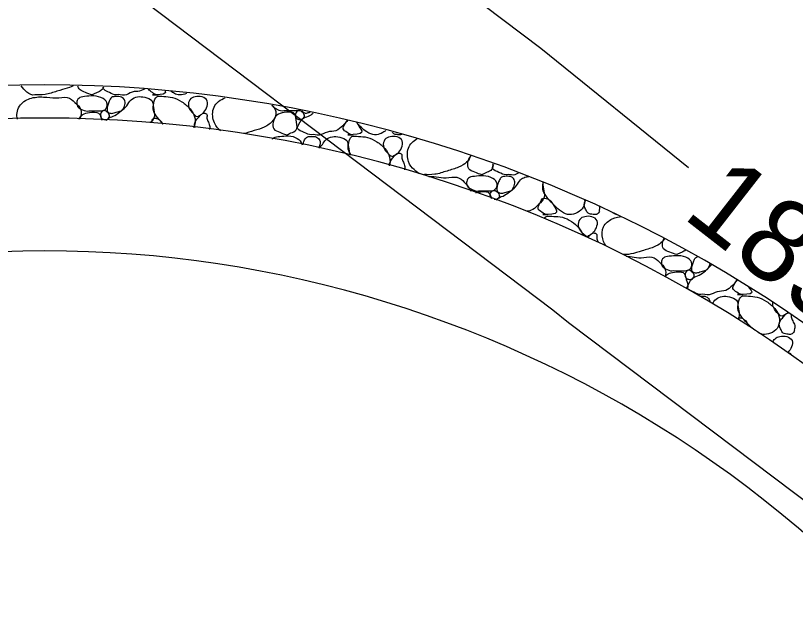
# Model space of a CAD drawing. Extents: x 1385284 to 1385995, y 1975154 to 1975620.
# Drawn here: x 1385467.93 to 1385491.41, y 1975551 to 1975568.95 of the extents above; entities that cross this region are included whole.
import ezdxf

# ---------------------------------------------------------------- set-up
doc = ezdxf.new("R2010")
doc.units = 0
for name, color, linetype in [('Default', 7, 'Continuous'), ('DTM_CONTOURS_MINOR', 7, 'Continuous'), ('R_Proposed Const Limits', 7, 'Continuous')]:
    doc.layers.add(name, color=color, linetype=linetype)

msp = doc.modelspace()

# ---------------------------------------------------------------- linework, layer by layer
at = {"layer": 'Default'}
for radius in [40, 39]:
    msp.add_arc((1385468.803, 1975526.863), radius, 324.5634, 101.9984, dxfattribs=at)
for points in [[(1385468.502, 1975566.57), (1385468.434, 1975566.535), (1385468.25, 1975566.649), (1385468.14, 1975566.768), (1385468.094, 1975566.834)], [(1385469.662, 1975566.836), (1385469.65, 1975566.829), (1385469.493, 1975566.763), (1385469.179, 1975566.681), (1385468.808, 1975566.552), (1385468.574, 1975566.567), (1385468.502, 1975566.57)], [(1385470.235, 1975566.566), (1385470.163, 1975566.576), (1385470.018, 1975566.645), (1385469.847, 1975566.701), (1385469.806, 1975566.8), (1385469.8, 1975566.83)], [(1385470.568, 1975566.798), (1385470.565, 1975566.771), (1385470.513, 1975566.693), (1385470.386, 1975566.638), (1385470.283, 1975566.59), (1385470.235, 1975566.566)], [(1385470.958, 1975566.566), (1385470.887, 1975566.561), (1385470.751, 1975566.641), (1385470.568, 1975566.716), (1385470.558, 1975566.792), (1385470.558, 1975566.798)], [(1385471.813, 1975566.745), (1385471.793, 1975566.731), (1385471.661, 1975566.655), (1385471.44, 1975566.682), (1385471.203, 1975566.506), (1385471.037, 1975566.586), (1385470.958, 1975566.566)], [(1385472.184, 1975566.566), (1385472.137, 1975566.565), (1385472.043, 1975566.636), (1385471.951, 1975566.699), (1385471.932, 1975566.74)], [(1385472.426, 1975566.684), (1385472.43, 1975566.667), (1385472.498, 1975566.561), (1385471.84, 1975566.574), (1385472.226, 1975566.563), (1385472.218, 1975566.566)], [(1385472.867, 1975566.566), (1385472.796, 1975566.562), (1385472.708, 1975566.601), (1385472.627, 1975566.654), (1385472.615, 1975566.662)], [(1385473.069, 1975566.609), (1385473.001, 1975566.579), (1385472.934, 1975566.565), (1385472.867, 1975566.566)], [(1385467.987, 1975565.831), (1385467.943, 1975565.953), (1385467.998, 1975566.257), (1385468.344, 1975566.489), (1385468.78, 1975566.517), (1385469.14, 1975566.445), (1385469.506, 1975566.538), (1385469.709, 1975566.333), (1385469.932, 1975566.144), (1385469.898, 1975565.923), (1385469.848, 1975565.828)], [(1385470.13, 1975566.083), (1385470.074, 1975566.059), (1385469.929, 1975566.117), (1385469.768, 1975566.203), (1385469.757, 1975566.369), (1385469.834, 1975566.501), (1385470.053, 1975566.52), (1385470.353, 1975566.55), (1385470.652, 1975566.427), (1385470.711, 1975566.241), (1385470.615, 1975566.074), (1385470.41, 1975566.082), (1385470.249, 1975566.077), (1385470.13, 1975566.083)], [(1385470.653, 1975565.794), (1385470.659, 1975565.802), (1385470.732, 1975565.882), (1385470.909, 1975565.927), (1385471.11, 1975566.086), (1385471.289, 1975566.228), (1385471.384, 1975566.434), (1385471.595, 1975566.527), (1385471.81, 1975566.501), (1385472.074, 1975566.415), (1385472.066, 1975566.187), (1385472.143, 1975565.915), (1385472.045, 1975565.782), (1385471.997, 1975565.728)], [(1385471.101, 1975566.083), (1385471.054, 1975566.068), (1385470.957, 1975566.045), (1385470.823, 1975565.991), (1385470.696, 1975566.033), (1385470.669, 1975566.139), (1385470.699, 1975566.253), (1385470.743, 1975566.38), (1385470.803, 1975566.505), (1385470.954, 1975566.521), (1385471.126, 1975566.517), (1385471.238, 1975566.39), (1385471.214, 1975566.23), (1385471.154, 1975566.113), (1385471.101, 1975566.083)], [(1385472.368, 1975565.685), (1385472.316, 1975565.742), (1385472.192, 1975565.878), (1385472.048, 1975566.09), (1385472.08, 1975566.316), (1385472.151, 1975566.558), (1385472.38, 1975566.506), (1385472.65, 1975566.511), (1385472.939, 1975566.366), (1385473.196, 1975566.155), (1385473.344, 1975565.896), (1385473.333, 1975565.665), (1385473.288, 1975565.59), (1385473.281, 1975565.579)], [(1385473.444, 1975565.937), (1385473.413, 1975565.863), (1385473.209, 1975566.044), (1385473.107, 1975566.223), (1385473.157, 1975566.443), (1385473.321, 1975566.515), (1385473.548, 1975566.523), (1385473.738, 1975566.398), (1385473.687, 1975566.159), (1385473.574, 1975565.995), (1385473.47, 1975565.947), (1385473.444, 1975565.937)], [(1385474.093, 1975565.485), (1385474.014, 1975565.556), (1385473.86, 1975565.736), (1385473.833, 1975566.224), (1385474.091, 1975566.429), (1385474.241, 1975566.474)], [(1385470.673, 1975565.817), (1385470.636, 1975565.817), (1385470.551, 1975565.815), (1385470.472, 1975565.896), (1385470.48, 1975566.014), (1385470.564, 1975566.116), (1385470.691, 1975566.066), (1385470.795, 1975565.906), (1385470.707, 1975565.846), (1385470.673, 1975565.817)], [(1385475.648, 1975566.251), (1385475.687, 1975566.209), (1385475.817, 1975566.081), (1385475.705, 1975565.768), (1385475.417, 1975565.578), (1385475.119, 1975565.491), (1385474.886, 1975565.418), (1385474.8, 1975565.397)], [(1385475.999, 1975566.083), (1385475.943, 1975566.059), (1385475.799, 1975566.117), (1385475.696, 1975566.183), (1385475.653, 1975566.247), (1385475.65, 1975566.251)], [(1385476.543, 1975565.817), (1385476.505, 1975565.817), (1385476.42, 1975565.815), (1385476.341, 1975565.896), (1385476.349, 1975566.014), (1385476.433, 1975566.116), (1385476.561, 1975566.066), (1385476.664, 1975565.906), (1385476.576, 1975565.846), (1385476.543, 1975565.817)], [(1385469.836, 1975565.828), (1385469.853, 1975565.866), (1385469.943, 1975565.995), (1385470.124, 1975566.036), (1385470.482, 1975566.067), (1385470.5, 1975565.885), (1385470.522, 1975565.8)], [(1385471.998, 1975565.728), (1385472.03, 1975565.779), (1385472.057, 1975565.878), (1385472.216, 1975565.852), (1385472.305, 1975565.782), (1385472.343, 1975565.707), (1385472.353, 1975565.686)], [(1385473.338, 1975565.572), (1385473.332, 1975565.586), (1385473.303, 1975565.64), (1385473.338, 1975565.776), (1385473.433, 1975565.887), (1385473.51, 1975565.976), (1385473.59, 1975566.032), (1385473.714, 1975565.981), (1385473.671, 1975565.864), (1385473.733, 1975565.738), (1385473.787, 1975565.614), (1385473.77, 1975565.541), (1385473.767, 1975565.522)], [(1385476.104, 1975565.363), (1385476.032, 1975565.373), (1385475.887, 1975565.442), (1385475.664, 1975565.513), (1385475.667, 1975565.741), (1385475.777, 1975565.987), (1385475.993, 1975566.036), (1385476.354, 1975566.066), (1385476.358, 1975565.824), (1385476.439, 1975565.512), (1385476.255, 1975565.435), (1385476.152, 1975565.387), (1385476.104, 1975565.363)], [(1385476.49, 1975566.09), (1385476.487, 1975566.089), (1385476.443, 1975566.079), (1385476.279, 1975566.082), (1385476.119, 1975566.077), (1385475.999, 1975566.083)], [(1385476.828, 1975565.363), (1385476.756, 1975565.358), (1385476.621, 1975565.438), (1385476.361, 1975565.527), (1385476.475, 1975565.696), (1385476.554, 1975565.883), (1385476.751, 1975565.906), (1385476.857, 1975565.987), (1385476.889, 1975566.014)], [(1385476.782, 1975566.034), (1385476.748, 1975566.026), (1385476.677, 1975565.995), (1385476.587, 1975566.023), (1385476.551, 1975566.068), (1385476.545, 1975566.08)], [(1385477.926, 1975565.804), (1385477.89, 1975565.75), (1385477.782, 1975565.64), (1385477.585, 1975565.446), (1385477.309, 1975565.479), (1385477.072, 1975565.303), (1385476.907, 1975565.383), (1385476.828, 1975565.363)], [(1385478.054, 1975565.363), (1385478.006, 1975565.362), (1385477.91, 1975565.435), (1385477.748, 1975565.528), (1385477.842, 1975565.686), (1385477.891, 1975565.768), (1385477.923, 1975565.805)], [(1385478.2, 1975565.73), (1385478.228, 1975565.68), (1385478.274, 1975565.594), (1385478.459, 1975565.354), (1385477.71, 1975565.371), (1385478.096, 1975565.36), (1385478.088, 1975565.363)], [(1385478.736, 1975565.363), (1385478.665, 1975565.359), (1385478.482, 1975565.444), (1385478.331, 1975565.585), (1385478.231, 1975565.691), (1385478.196, 1975565.731)], [(1385479.075, 1975565.493), (1385479.051, 1975565.472), (1385478.939, 1975565.393), (1385478.821, 1975565.362), (1385478.736, 1975565.363)], [(1385479.544, 1975565.367), (1385479.516, 1975565.361), (1385479.439, 1975565.366), (1385479.329, 1975565.37), (1385479.285, 1975565.424), (1385479.276, 1975565.439)], [(1385475.663, 1975565.231), (1385475.675, 1975565.249), (1385475.725, 1975565.299), (1385475.923, 1975565.317), (1385476.222, 1975565.347), (1385476.485, 1975565.233), (1385476.552, 1975565.097), (1385476.558, 1975565.06)], [(1385476.572, 1975565.057), (1385476.572, 1975565.058), (1385476.584, 1975565.096), (1385476.612, 1975565.177), (1385476.673, 1975565.302), (1385476.823, 1975565.318), (1385476.995, 1975565.314), (1385477.108, 1975565.187), (1385477.097, 1975565.059), (1385477.06, 1975564.984), (1385477.05, 1975564.965)], [(1385477.057, 1975564.964), (1385477.089, 1975564.996), (1385477.174, 1975565.062), (1385477.253, 1975565.231), (1385477.464, 1975565.324), (1385477.68, 1975565.298), (1385477.943, 1975565.212), (1385477.934, 1975565.001), (1385477.982, 1975564.832), (1385477.978, 1975564.755)], [(1385478.036, 1975564.739), (1385478, 1975564.799), (1385477.92, 1975564.919), (1385477.949, 1975565.113), (1385478.02, 1975565.355), (1385478.249, 1975565.303), (1385478.519, 1975565.308), (1385478.808, 1975565.163), (1385479.065, 1975564.952), (1385479.208, 1975564.697), (1385479.208, 1975564.493), (1385479.18, 1975564.43)], [(1385479.314, 1975564.734), (1385479.283, 1975564.66), (1385479.078, 1975564.841), (1385478.976, 1975565.02), (1385479.026, 1975565.24), (1385479.191, 1975565.312), (1385479.418, 1975565.32), (1385479.608, 1975565.195), (1385479.556, 1975564.956), (1385479.443, 1975564.792), (1385479.339, 1975564.744), (1385479.314, 1975564.734)], [(1385480.102, 1975564.181), (1385480.068, 1975564.199), (1385479.922, 1975564.303), (1385479.735, 1975564.512), (1385479.691, 1975564.988), (1385479.911, 1975565.185), (1385480.023, 1975565.237)], [(1385479.185, 1975564.429), (1385479.176, 1975564.469), (1385479.211, 1975564.577), (1385479.302, 1975564.684), (1385479.379, 1975564.773), (1385479.459, 1975564.829), (1385479.584, 1975564.778), (1385479.541, 1975564.661), (1385479.603, 1975564.535), (1385479.662, 1975564.409), (1385479.637, 1975564.329), (1385479.634, 1975564.307)], [(1385481.626, 1975564.726), (1385481.61, 1975564.661), (1385481.528, 1975564.525), (1385481.286, 1975564.375), (1385480.918, 1975564.275), (1385480.546, 1975564.146), (1385480.313, 1975564.161), (1385480.241, 1975564.164)], [(1385481.973, 1975564.16), (1385481.901, 1975564.17), (1385481.757, 1975564.239), (1385481.533, 1975564.31), (1385481.536, 1975564.533), (1385481.58, 1975564.659), (1385481.639, 1975564.721)], [(1385482.292, 1975564.491), (1385482.31, 1975564.427), (1385482.28, 1975564.298), (1385482.124, 1975564.232), (1385482.022, 1975564.184), (1385481.973, 1975564.16)], [(1385482.697, 1975564.16), (1385482.625, 1975564.155), (1385482.49, 1975564.235), (1385482.234, 1975564.323), (1385482.313, 1975564.444), (1385482.331, 1975564.477)], [(1385480.241, 1975564.164), (1385480.229, 1975564.158), (1385480.216, 1975564.155), (1385480.202, 1975564.154)], [(1385480.37, 1975564.108), (1385480.399, 1975564.11), (1385480.597, 1975564.103), (1385480.878, 1975564.039), (1385481.245, 1975564.132), (1385481.448, 1975563.927), (1385481.59, 1975563.781), (1385481.626, 1975563.681), (1385481.63, 1975563.665)], [(1385481.868, 1975563.677), (1385481.813, 1975563.653), (1385481.668, 1975563.711), (1385481.506, 1975563.797), (1385481.496, 1975563.964), (1385481.573, 1975564.095), (1385481.792, 1975564.114), (1385482.092, 1975564.144), (1385482.39, 1975564.021), (1385482.45, 1975563.835), (1385482.354, 1975563.669), (1385482.148, 1975563.676), (1385481.988, 1975563.671), (1385481.868, 1975563.677)], [(1385482.397, 1975563.395), (1385482.401, 1975563.4), (1385482.473, 1975563.476), (1385482.648, 1975563.521), (1385482.848, 1975563.68), (1385483.027, 1975563.822), (1385483.122, 1975564.028), (1385483.267, 1975564.087), (1385483.36, 1975564.103), (1385483.384, 1975564.106)], [(1385482.839, 1975563.677), (1385482.792, 1975563.662), (1385482.696, 1975563.639), (1385482.561, 1975563.585), (1385482.435, 1975563.627), (1385482.407, 1975563.733), (1385482.438, 1975563.847), (1385482.481, 1975563.974), (1385482.542, 1975564.099), (1385482.692, 1975564.115), (1385482.864, 1975564.111), (1385482.977, 1975563.984), (1385482.953, 1975563.824), (1385482.892, 1975563.707), (1385482.839, 1975563.677)], [(1385483.079, 1975564.213), (1385483.036, 1975564.196), (1385482.922, 1975564.11), (1385482.776, 1975564.18), (1385482.697, 1975564.16)], [(1385483.79, 1975563.945), (1385483.804, 1975563.893), (1385483.815, 1975563.747), (1385483.891, 1975563.47), (1385483.676, 1975563.263), (1385483.509, 1975563.087), (1385483.375, 1975563.066), (1385483.316, 1975563.059)], [(1385484.606, 1975562.957), (1385484.534, 1975562.954), (1385484.352, 1975563.038), (1385484.155, 1975563.22), (1385483.945, 1975563.444), (1385483.786, 1975563.684), (1385483.803, 1975563.863), (1385483.815, 1975563.932), (1385483.815, 1975563.934)], [(1385481.783, 1975563.611), (1385481.812, 1975563.622), (1385481.922, 1975563.652), (1385482.19, 1975563.671), (1385482.232, 1975563.515), (1385482.248, 1975563.447)], [(1385482.281, 1975563.435), (1385482.258, 1975563.45), (1385482.21, 1975563.498), (1385482.218, 1975563.608), (1385482.303, 1975563.71), (1385482.43, 1975563.66), (1385482.533, 1975563.5), (1385482.445, 1975563.44), (1385482.412, 1975563.411)], [(1385482.412, 1975563.411), (1385482.388, 1975563.411), (1385482.364, 1975563.411), (1385482.341, 1975563.414)], [(1385483.923, 1975562.957), (1385483.876, 1975562.956), (1385483.78, 1975563.029), (1385483.617, 1975563.122), (1385483.726, 1975563.307), (1385483.774, 1975563.472), (1385483.955, 1975563.446), (1385484.074, 1975563.341), (1385484.142, 1975563.197), (1385484.329, 1975562.948), (1385483.579, 1975562.965), (1385483.965, 1975562.955), (1385483.957, 1975562.957)], [(1385485.063, 1975563.406), (1385485.078, 1975563.343), (1385485.041, 1975563.169), (1385484.859, 1975563), (1385484.69, 1975562.956), (1385484.606, 1975562.957)], [(1385485.509, 1975563.062), (1385485.499, 1975563.037), (1385485.451, 1975562.947), (1385485.328, 1975562.962), (1385485.15, 1975562.981), (1385485.112, 1975563.097), (1385485.038, 1975563.206), (1385485.057, 1975563.323), (1385485.09, 1975563.377), (1385485.099, 1975563.39)], [(1385485.502, 1975563.203), (1385485.504, 1975563.192), (1385485.526, 1975563.149), (1385485.491, 1975563.092), (1385485.509, 1975563.062)], [(1385483.843, 1975562.839), (1385483.854, 1975562.861), (1385483.927, 1975562.935), (1385484.118, 1975562.897), (1385484.388, 1975562.902), (1385484.677, 1975562.757), (1385484.899, 1975562.574), (1385484.993, 1975562.4), (1385485.024, 1975562.323)], [(1385485.183, 1975562.328), (1385485.152, 1975562.254), (1385484.947, 1975562.435), (1385484.845, 1975562.614), (1385484.896, 1975562.834), (1385485.06, 1975562.906), (1385485.287, 1975562.914), (1385485.477, 1975562.789), (1385485.426, 1975562.55), (1385485.313, 1975562.386), (1385485.209, 1975562.338), (1385485.183, 1975562.328)], [(1385485.716, 1975562.003), (1385485.69, 1975562.038), (1385485.581, 1975562.199), (1385485.575, 1975562.624), (1385485.895, 1975562.855), (1385486.108, 1975562.894), (1385486.159, 1975562.899)], [(1385486.045, 1975562.952), (1385486.003, 1975562.959), (1385485.956, 1975562.983), (1385485.915, 1975563.012)], [(1385485.155, 1975562.262), (1385485.164, 1975562.273), (1385485.198, 1975562.31), (1385485.248, 1975562.367), (1385485.328, 1975562.423), (1385485.453, 1975562.372), (1385485.41, 1975562.256), (1385485.452, 1975562.177), (1385485.471, 1975562.116)], [(1385487.466, 1975562.239), (1385487.45, 1975562.203), (1385487.379, 1975562.102), (1385487.155, 1975561.969), (1385486.787, 1975561.869), (1385486.451, 1975561.751), (1385486.254, 1975561.752), (1385486.217, 1975561.753)], [(1385487.842, 1975561.754), (1385487.771, 1975561.764), (1385487.626, 1975561.833), (1385487.403, 1975561.904), (1385487.403, 1975562.101), (1385487.433, 1975562.202), (1385487.456, 1975562.244)], [(1385488.109, 1975561.889), (1385488.071, 1975561.862), (1385487.981, 1975561.821), (1385487.891, 1975561.778), (1385487.842, 1975561.754)], [(1385486.317, 1975561.703), (1385486.32, 1975561.703), (1385486.493, 1975561.695), (1385486.747, 1975561.633), (1385487.114, 1975561.726), (1385487.317, 1975561.521), (1385487.516, 1975561.346), (1385487.511, 1975561.166), (1385487.488, 1975561.09)], [(1385487.737, 1975561.271), (1385487.682, 1975561.247), (1385487.537, 1975561.305), (1385487.376, 1975561.391), (1385487.365, 1975561.558), (1385487.442, 1975561.689), (1385487.661, 1975561.708), (1385487.961, 1975561.738), (1385488.26, 1975561.615), (1385488.319, 1975561.429), (1385488.223, 1975561.263), (1385488.017, 1975561.27), (1385487.857, 1975561.265), (1385487.737, 1975561.271)], [(1385488.709, 1975561.271), (1385488.661, 1975561.256), (1385488.565, 1975561.233), (1385488.431, 1975561.179), (1385488.304, 1975561.221), (1385488.277, 1975561.327), (1385488.307, 1975561.441), (1385488.35, 1975561.568), (1385488.393, 1975561.659), (1385488.448, 1975561.687), (1385488.462, 1975561.691)], [(1385488.566, 1975560.551), (1385488.494, 1975560.546), (1385488.359, 1975560.626), (1385488.099, 1975560.715), (1385488.213, 1975560.884), (1385488.292, 1975561.071), (1385488.517, 1975561.115), (1385488.717, 1975561.274), (1385488.831, 1975561.39), (1385488.89, 1975561.452), (1385488.89, 1975561.452)], [(1385488.836, 1975561.482), (1385488.834, 1975561.458), (1385488.804, 1975561.382), (1385488.762, 1975561.301), (1385488.709, 1975561.271)], [(1385487.488, 1975561.09), (1385487.498, 1975561.102), (1385487.576, 1975561.189), (1385487.732, 1975561.224), (1385488.093, 1975561.254), (1385488.097, 1975561.015), (1385488.208, 1975560.787), (1385488.15, 1975560.72)], [(1385488.281, 1975561.005), (1385488.244, 1975561.005), (1385488.159, 1975561.003), (1385488.08, 1975561.084), (1385488.088, 1975561.202), (1385488.172, 1975561.305), (1385488.299, 1975561.254), (1385488.403, 1975561.094), (1385488.315, 1975561.034), (1385488.281, 1975561.005)], [(1385489.661, 1975560.987), (1385489.626, 1975560.935), (1385489.519, 1975560.827), (1385489.324, 1975560.634), (1385489.047, 1975560.667), (1385488.811, 1975560.492), (1385488.645, 1975560.571), (1385488.566, 1975560.551)], [(1385489.792, 1975560.551), (1385489.745, 1975560.55), (1385489.649, 1975560.623), (1385489.486, 1975560.716), (1385489.579, 1975560.872), (1385489.628, 1975560.953), (1385489.657, 1975560.989)], [(1385490, 1975560.78), (1385490.002, 1975560.775), (1385490.024, 1975560.725), (1385490.198, 1975560.542), (1385489.448, 1975560.559), (1385489.834, 1975560.549), (1385489.826, 1975560.551)], [(1385488.538, 1975560.5), (1385488.607, 1975560.505), (1385488.735, 1975560.5), (1385488.82, 1975560.403), (1385488.835, 1975560.343), (1385488.837, 1975560.318)], [(1385488.91, 1975560.273), (1385488.939, 1975560.311), (1385489.002, 1975560.423), (1385489.203, 1975560.512), (1385489.418, 1975560.486), (1385489.682, 1975560.4), (1385489.674, 1975560.172), (1385489.74, 1975559.947), (1385489.691, 1975559.833), (1385489.675, 1975559.807)], [(1385490.183, 1975559.473), (1385490.132, 1975559.512), (1385490.005, 1975559.633), (1385489.814, 1975559.835), (1385489.655, 1975560.075), (1385489.688, 1975560.301), (1385489.758, 1975560.543), (1385489.988, 1975560.491), (1385490.257, 1975560.496), (1385490.547, 1975560.351), (1385490.804, 1975560.14), (1385490.952, 1975559.881), (1385490.914, 1975559.564), (1385490.728, 1975559.391), (1385490.559, 1975559.347), (1385490.475, 1975559.348)], [(1385491.052, 1975559.922), (1385491.021, 1975559.848), (1385490.816, 1975560.029), (1385490.73, 1975560.188), (1385490.726, 1975560.289), (1385490.729, 1975560.311)], [(1385491.379, 1975559.453), (1385491.368, 1975559.428), (1385491.32, 1975559.338), (1385491.198, 1975559.353), (1385491.019, 1975559.372), (1385490.982, 1975559.488), (1385490.907, 1975559.597), (1385490.946, 1975559.761), (1385491.041, 1975559.872), (1385491.118, 1975559.961), (1385491.175, 1975559.994), (1385491.201, 1975559.997), (1385491.202, 1975559.997)], [(1385491.183, 1975560.01), (1385491.165, 1975559.992), (1385491.122, 1975559.952), (1385491.078, 1975559.932), (1385491.052, 1975559.922)], [(1385489.676, 1975559.806), (1385489.69, 1975559.821), (1385489.716, 1975559.862), (1385489.824, 1975559.837), (1385489.933, 1975559.744), (1385489.973, 1975559.646), (1385489.99, 1975559.601)], [(1385491.276, 1975559.948), (1385491.282, 1975559.928), (1385491.281, 1975559.846), (1385491.341, 1975559.723), (1385491.424, 1975559.587), (1385491.36, 1975559.483), (1385491.379, 1975559.453)], [(1385490.475, 1975559.348), (1385490.413, 1975559.345), (1385490.352, 1975559.367), (1385490.291, 1975559.402)], [(1385490.729, 1975559.111), (1385490.734, 1975559.137), (1385490.784, 1975559.232), (1385490.929, 1975559.298), (1385491.156, 1975559.305), (1385491.346, 1975559.18), (1385491.305, 1975558.962), (1385491.232, 1975558.853), (1385491.178, 1975558.802)], [(1385491.191, 1975558.792), (1385491.194, 1975558.793), (1385491.22, 1975558.799), (1385491.274, 1975558.775), (1385491.278, 1975558.739), (1385491.277, 1975558.731)]]:
    msp.add_open_spline(points, degree=3, dxfattribs=at)
at = {"layer": 'DTM_CONTOURS_MINOR'}
for points in [[(1385488.189, 1975564.366), (1385483.74, 1975567.963), (1385474.707, 1975574.791), (1385467.529, 1975580.634), (1385462.767, 1975583.789), (1385453.007, 1975588.282), (1385448.704, 1975591.02), (1385437.889, 1975595.952), (1385433.309, 1975597.404), (1385425.221, 1975597.918), (1385419.709, 1975599.94), (1385412.905, 1975600.422), (1385407.929, 1975593.394), (1385399.227, 1975591.016), (1385396.775, 1975581.115)], [(1385534.545, 1975545.92), (1385529.729, 1975545.685), (1385519.689, 1975538.171), (1385502.211, 1975546.507), (1385502.041, 1975546.577), (1385501.882, 1975546.641), (1385484.577, 1975559.699), (1385484.107, 1975560.079), (1385467.301, 1975572.783), (1385466.481, 1975573.451), (1385456.805, 1975579.862), (1385454.291, 1975581.019), (1385445.143, 1975586.839), (1385441.234, 1975588.622), (1385430.98, 1975591.874), (1385429.467, 1975591.97), (1385421.762, 1975594.796), (1385414.234, 1975590.496), (1385407.886, 1975581.531), (1385406.491, 1975581.15), (1385406.184, 1975579.91)]]:
    msp.add_lwpolyline(points, dxfattribs=at)
at = {"layer": 'R_Proposed Const Limits'}
msp.add_arc((1385468.803, 1975526.863), 35, 324.5634, 101.9984, dxfattribs=at)

# ---------------------------------------------------------------- texts
at = {"layer": 'Default'}
msp.add_text('189', height=2.5, rotation=322.0937, dxfattribs=at).set_placement((1385487.965, 1975562.899))

doc.saveas('drawing.dxf')
